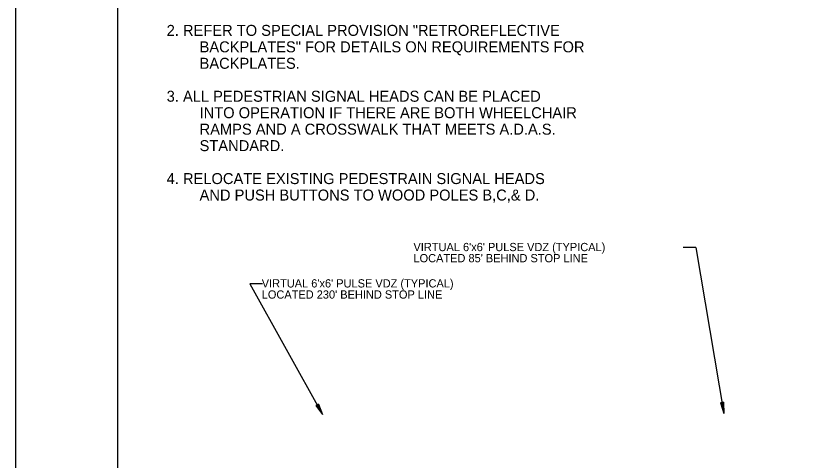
# Model space of a CAD drawing. Extents: x 662183 to 663183, y 642099 to 642739.
# Drawn here: x 662182.6 to 662473, y 642419.3 to 642581.1 of the extents above; entities that cross this region are included whole.
import ezdxf

# ---------------------------------------------------------------- set-up
doc = ezdxf.new("R2010")
doc.units = 0
for name, color, linetype in [('Default', 7, 'Continuous'), ('R_Border', 7, 'Continuous'), ('R_No Plot', 7, 'Continuous'), ('T_Drafting', 7, 'Continuous')]:
    doc.layers.add(name, color=color, linetype=linetype)

msp = doc.modelspace()

# ---------------------------------------------------------------- linework, layer by layer
at = {"layer": 'R_Border'}
msp.add_line((662219.86, 642111.24), (662219.86, 642727.62), dxfattribs=at)
at = {"layer": 'R_No Plot'}
msp.add_lwpolyline([(662182.64, 642739.3), (663182.66, 642739.3), (663182.66, 642099.29), (662182.64, 642099.29)], close=True, dxfattribs=at)
at = {"layer": 'T_Drafting'}
for p, q in [((662430.62, 642496.8), (662426.03, 642496.8)), ((662430.62, 642496.8), (662440.83, 642436.28)), ((662267.95, 642483.5), (662294.46, 642435.92)), ((662272.54, 642483.5), (662267.95, 642483.5)), ((662293.04, 642439.7), (662291.99, 642439.12)), ((662291.99, 642439.12), (662294.46, 642435.92)), ((662292.08, 642439.17), (662294.13, 642436.5)), ((662292.16, 642439.22), (662293.8, 642437.1)), ((662292.25, 642439.27), (662293.48, 642437.68)), ((662292.34, 642439.32), (662293.15, 642438.28)), ((662292.43, 642439.37), (662292.82, 642438.86)), ((662292.59, 642439.46), (662292.82, 642438.86)), ((662292.68, 642439.51), (662293.15, 642438.28)), ((662292.77, 642439.56), (662293.48, 642437.68)), ((662292.86, 642439.61), (662293.8, 642437.1)), ((662292.95, 642439.65), (662294.13, 642436.5)), ((662293.04, 642439.7), (662294.46, 642435.92)), ((662440.76, 642440.33), (662439.57, 642440.13)), ((662439.57, 642440.13), (662440.83, 642436.28)), ((662439.67, 642440.14), (662440.72, 642436.94)), ((662439.77, 642440.16), (662440.6, 642437.62)), ((662439.87, 642440.18), (662440.49, 642438.28)), ((662439.97, 642440.19), (662440.38, 642438.94)), ((662440.07, 642440.21), (662440.27, 642439.6)), ((662440.26, 642440.24), (662440.27, 642439.6)), ((662440.35, 642440.26), (662440.38, 642438.94)), ((662440.46, 642440.28), (662440.49, 642438.28)), ((662440.56, 642440.29), (662440.6, 642437.62)), ((662440.66, 642440.31), (662440.72, 642436.94)), ((662440.76, 642440.33), (662440.83, 642436.28))]:
    msp.add_line(p, q, dxfattribs=at)

# ---------------------------------------------------------------- texts
at = {"layer": 'Default'}
for s, p in [('2. REFER TO SPECIAL PROVISION "RETROREFLECTIVE', (662237.62, 642573.86)), ('BACKPLATES" FOR DETAILS ON REQUIREMENTS FOR ', (662249.62, 642567.86)), ('BACKPLATES.', (662249.62, 642561.86)), ('3. ALL PEDESTRIAN SIGNAL HEADS CAN BE PLACED', (662237.62, 642549.86)), ('INTO OPERATION IF THERE ARE BOTH WHEELCHAIR', (662249.62, 642543.86)), ('RAMPS AND A CROSSWALK THAT MEETS A.D.A.S.', (662249.62, 642537.86)), ('STANDARD.', (662249.62, 642531.86)), ('4. RELOCATE EXISTING PEDESTRAIN SIGNAL HEADS', (662237.62, 642519.86)), ('AND PUSH BUTTONS TO WOOD POLES B,C,& D.', (662249.62, 642513.86))]:
    msp.add_text(s, height=4, dxfattribs=at).set_placement(p)
at = {"layer": 'T_Drafting'}
for s, p in [("VIRTUAL 6'x6' PULSE VDZ (TYPICAL)", (662327.63, 642495.42)), ("LOCATED 85' BEHIND STOP LINE", (662327.63, 642491.36)), ("VIRTUAL 6'x6' PULSE VDZ (TYPICAL)", (662272.29, 642482.18)), ("LOCATED 230' BEHIND STOP LINE", (662272.29, 642478.12))]:
    msp.add_text(s, height=3, dxfattribs=at).set_placement(p)

doc.saveas('drawing.dxf')
